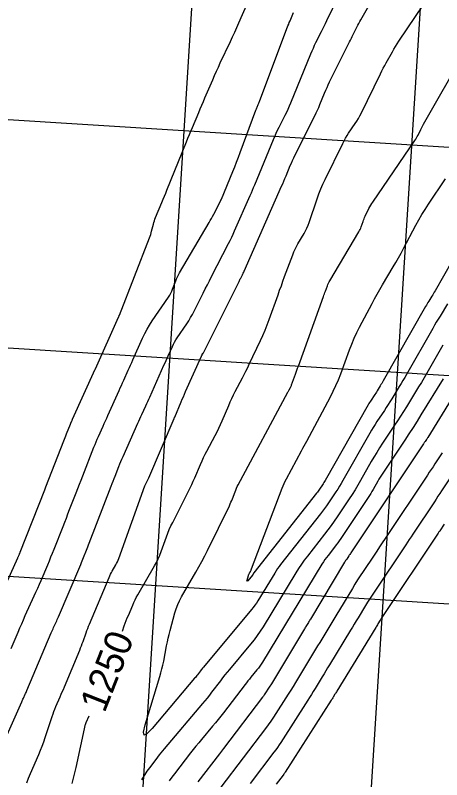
# Model space of a CAD drawing. Extents: x 658976 to 668721, y 639543 to 647196.
# Drawn here: x 661943.1 to 662036.6, y 641838 to 642005.8 of the extents above; entities that cross this region are included whole.
import ezdxf

# ---------------------------------------------------------------- set-up
doc = ezdxf.new("R2010")
doc.units = 0
for name, color, linetype in [('Ex_Contour Labels', 7, 'Continuous'), ('Ex_Major Contours', 7, 'Continuous'), ('Ex_Minor Contours', 7, 'Continuous'), ('R_Grid', 7, 'Continuous')]:
    doc.layers.add(name, color=color, linetype=linetype)

msp = doc.modelspace()

# ---------------------------------------------------------------- linework, layer by layer
at = {"layer": 'Ex_Major Contours'}
for points in [[(661966.58, 641870.64), (661966.98, 641871.77), (661967.19, 641872.35), (661967.41, 641872.93), (661967.63, 641873.5), (661967.87, 641874.07), (661968.82, 641876.35), (661969.07, 641876.91), (661969.34, 641877.47), (661969.62, 641878.02), (661969.92, 641878.55), (661973.62, 641884.96), (661974.03, 641885.71), (661974.41, 641886.48), (661974.75, 641887.27), (661975.06, 641888.07), (661976.23, 641891.31), (661976.54, 641892.12), (661976.86, 641892.91), (661977.22, 641893.7), (661977.6, 641894.47), (661981.08, 641901.31), (661981.44, 641902.03), (661981.79, 641902.76), (661982.12, 641903.5), (661982.45, 641904.24), (661983.72, 641907.22), (661984.04, 641907.96), (661984.38, 641908.69), (661984.74, 641909.42), (661985.11, 641910.13), (661986.93, 641913.56), (661987.33, 641914.35), (661987.73, 641915.15), (661988.1, 641915.96), (661988.46, 641916.77), (661989.88, 641920.15), (661990.21, 641920.92), (661990.57, 641921.69), (661990.94, 641922.45), (661991.32, 641923.2), (661992.9, 641926.19), (661993.29, 641926.94), (661993.67, 641927.7), (661994.05, 641928.46), (661994.41, 641929.22), (661996.85, 641934.41), (661997.37, 641935.53), (661997.85, 641936.67), (661998.31, 641937.82), (661998.74, 641938.98), (662000.7, 641944.42), (662001.06, 641945.43), (662001.43, 641946.43), (662001.79, 641947.44), (662002.16, 641948.45), (662003.92, 641953.23), (662004.16, 641953.85), (662004.43, 641954.45), (662004.73, 641955.04), (662005.05, 641955.62), (662006.41, 641957.9), (662006.74, 641958.48), (662007.03, 641959.07), (662007.29, 641959.68), (662007.52, 641960.3), (662009.28, 641965.52), (662009.66, 641966.6), (662010.08, 641967.66), (662010.53, 641968.7), (662011.01, 641969.73), (662014.9, 641977.67), (662015.19, 641978.25), (662015.5, 641978.81), (662015.84, 641979.36), (662016.19, 641979.89), (662017.65, 641982.02), (662018, 641982.56), (662018.33, 641983.11), (662018.64, 641983.67), (662018.94, 641984.25), (662023.17, 641992.95), (662023.47, 641993.56), (662023.78, 641994.17), (662024.11, 641994.77), (662024.44, 641995.36), (662025.79, 641997.74), (662026.13, 641998.33), (662026.49, 641998.92), (662026.85, 641999.49), (662027.22, 642000.07), (662034.36, 642010.77)], [(662036.85, 641933.37), (662036.27, 641932.35), (662033.94, 641928.26), (662033.35, 641927.24), (662032.76, 641926.22), (662032.15, 641925.21), (662031.54, 641924.21), (662028.85, 641919.82), (662028.22, 641918.81), (662027.59, 641917.8), (662026.94, 641916.8), (662026.29, 641915.81), (662023.65, 641911.85), (662023, 641910.86), (662022.36, 641909.85), (662021.75, 641908.83), (662021.15, 641907.81), (662018.79, 641903.66), (662018.2, 641902.64), (662017.59, 641901.63), (662016.96, 641900.63), (662016.32, 641899.64), (662013.7, 641895.71), (662013.03, 641894.74), (662012.35, 641893.78), (662011.65, 641892.83), (662010.93, 641891.89), (662007.15, 641887.1), (662006.47, 641886.21), (662005.82, 641885.29), (662005.19, 641884.36), (662004.59, 641883.41), (661997.43, 641871.59), (661996.8, 641870.6), (661996.14, 641869.63), (661995.44, 641868.69), (661994.7, 641867.77), (661990.07, 641862.23), (661989.56, 641861.61), (661989.05, 641860.99), (661988.56, 641860.36), (661988.07, 641859.73), (661986.13, 641857.19), (661985.64, 641856.56), (661985.15, 641855.93), (661984.64, 641855.31), (661984.13, 641854.7), (661975.74, 641844.76), (661975.37, 641844.32), (661975.01, 641843.88), (661974.66, 641843.44), (661974.3, 641842.99), (661972.77, 641841.01), (661972.49, 641840.64), (661972.22, 641840.27), (661971.96, 641839.89), (661971.71, 641839.51), (661970.72, 641837.96)], [(662037.13, 641894.07), (662036.17, 641892.63), (662036.09, 641892.51), (662036.01, 641892.39), (662035.93, 641892.27), (662035.85, 641892.15), (662023.6, 641873.79), (662023.47, 641873.59), (662023.34, 641873.4), (662023.22, 641873.2), (662023.1, 641873), (662022.61, 641872.19), (662022.49, 641871.99), (662022.37, 641871.79), (662022.25, 641871.59), (662022.13, 641871.39), (662013.61, 641857.44), (662013.5, 641857.27), (662013.4, 641857.11), (662013.3, 641856.94), (662013.2, 641856.78), (662012.8, 641856.11), (662012.7, 641855.95), (662012.6, 641855.78), (662012.5, 641855.62), (662012.39, 641855.45), (662002.28, 641839.67), (662002.17, 641839.51), (662002.07, 641839.35), (662001.95, 641839.2), (662001.84, 641839.04), (662000.3, 641837.02)], [(661955.52, 641837.17), (661955.85, 641838.33), (661956.15, 641839.49), (661956.42, 641840.66), (661958.5, 641850.19), (661958.51, 641850.22), (661958.51, 641850.25), (661958.52, 641850.28), (661958.53, 641850.31), (661958.57, 641850.43), (661958.58, 641850.45), (661958.59, 641850.48), (661958.6, 641850.51), (661958.61, 641850.54), (661959.25, 641852.03)]]:
    msp.add_lwpolyline(points, dxfattribs=at)
at = {"layer": 'Ex_Minor Contours'}
for points in [[(661945.58, 641837.33), (661945.99, 641838.34), (661946.41, 641839.35), (661948.21, 641843.54), (661948.59, 641844.46), (661948.96, 641845.4), (661949.3, 641846.33), (661949.63, 641847.28), (661951.17, 641851.88), (661951.36, 641852.43), (661951.56, 641852.98), (661951.77, 641853.52), (661952, 641854.06), (661952.92, 641856.21), (661953.15, 641856.75), (661953.38, 641857.29), (661953.61, 641857.82), (661953.84, 641858.36), (661957.21, 641866.45), (661957.4, 641866.92), (661957.58, 641867.39), (661957.76, 641867.87), (661957.93, 641868.34), (661958.6, 641870.26), (661958.78, 641870.74), (661958.95, 641871.21), (661959.14, 641871.68), (661959.33, 641872.15), (661963.66, 641882.42), (661963.81, 641882.78), (661963.98, 641883.12), (661964.16, 641883.47), (661964.34, 641883.81), (661965.12, 641885.15), (661965.3, 641885.49), (661965.47, 641885.83), (661965.63, 641886.19), (661965.77, 641886.55), (661971.52, 641902.5), (661971.58, 641902.66), (661971.64, 641902.81), (661971.71, 641902.96), (661971.78, 641903.1), (661972.08, 641903.69), (661972.15, 641903.83), (661972.22, 641903.98), (661972.29, 641904.13), (661972.35, 641904.28), (661977.89, 641917.27), (661977.91, 641917.3), (661977.92, 641917.33), (661977.93, 641917.35), (661977.95, 641917.38), (661978, 641917.48), (661978.01, 641917.51), (661978.03, 641917.54), (661978.04, 641917.56), (661978.05, 641917.59), (661979.46, 641920.93), (661979.7, 641921.5), (661979.94, 641922.06), (661980.19, 641922.62), (661980.44, 641923.18), (661983.91, 641930.95), (661983.94, 641931.02), (661983.97, 641931.08), (661984.03, 641931.21), (661984.05, 641931.25), (661984.06, 641931.28), (661984.08, 641931.31), (661984.1, 641931.34), (661984.23, 641931.53), (661984.26, 641931.57), (661984.29, 641931.62), (661984.31, 641931.66), (661984.34, 641931.71), (661992.15, 641947.36), (661992.25, 641947.55), (661992.34, 641947.73), (661992.43, 641947.92), (661992.53, 641948.1), (661992.91, 641948.83), (661993, 641949.02), (661993.09, 641949.2), (661993.18, 641949.39), (661993.26, 641949.58), (662001.49, 641968.25), (662001.74, 641968.81), (662001.98, 641969.37), (662002.22, 641969.94), (662002.46, 641970.51), (662003.4, 641972.78), (662003.64, 641973.34), (662003.89, 641973.91), (662004.15, 641974.46), (662004.42, 641975.02), (662008.77, 641983.73), (662009.07, 641984.34), (662009.35, 641984.95), (662009.63, 641985.57), (662009.89, 641986.19), (662010.91, 641988.69), (662011.18, 641989.31), (662011.45, 641989.93), (662011.73, 641990.54), (662012.03, 641991.14), (662016.4, 641999.92), (662016.6, 642000.33), (662016.8, 642000.73), (662017, 642001.14), (662017.2, 642001.55), (662017.99, 642003.18), (662018.19, 642003.58), (662018.4, 642003.98), (662018.62, 642004.38), (662018.84, 642004.78), (662026.11, 642017.5)], [(661937.41, 641839.27), (661944.47, 641855.08), (661944.57, 641855.29), (661944.66, 641855.5), (661944.75, 641855.71), (661944.85, 641855.92), (661945.23, 641856.75), (661945.32, 641856.96), (661945.42, 641857.17), (661945.51, 641857.38), (661945.6, 641857.59), (661950.96, 641870.24), (661951.09, 641870.54), (661951.22, 641870.83), (661951.35, 641871.13), (661951.48, 641871.42), (661952.02, 641872.6), (661952.15, 641872.89), (661952.28, 641873.18), (661952.41, 641873.48), (661952.53, 641873.78), (661957.43, 641885.26), (661957.59, 641885.65), (661957.75, 641886.04), (661957.91, 641886.42), (661958.06, 641886.81), (661958.67, 641888.37), (661958.82, 641888.76), (661958.98, 641889.15), (661959.13, 641889.54), (661959.28, 641889.93), (661964.11, 641902.46), (661964.32, 641903), (661964.53, 641903.54), (661964.74, 641904.08), (661964.95, 641904.62), (661965.8, 641906.78), (661966.02, 641907.32), (661966.24, 641907.86), (661966.47, 641908.39), (661966.7, 641908.92), (661969.98, 641916.25), (661970.2, 641916.73), (661970.41, 641917.21), (661970.62, 641917.69), (661970.84, 641918.16), (661971.7, 641920.07), (661971.91, 641920.55), (661972.12, 641921.02), (661972.34, 641921.5), (661972.55, 641921.98), (661975.69, 641928.99), (661975.92, 641929.5), (661976.15, 641930.01), (661976.38, 641930.52), (661976.6, 641931.03), (661977.52, 641933.07), (661977.76, 641933.57), (661978.02, 641934.06), (661978.3, 641934.54), (661978.61, 641935.01), (661980.68, 641938.07), (661981.12, 641938.74), (661981.54, 641939.42), (661981.93, 641940.12), (661982.3, 641940.83), (661984.29, 641944.81), (661984.74, 641945.72), (661985.2, 641946.62), (661985.65, 641947.52), (661986.12, 641948.41), (661989.86, 641955.68), (661990.21, 641956.36), (661990.54, 641957.05), (661990.87, 641957.74), (661991.18, 641958.44), (661994.6, 641966.19), (661994.86, 641966.78), (661995.11, 641967.38), (661995.36, 641967.97), (661995.61, 641968.57), (661999.72, 641978.51), (662000.01, 641979.19), (662000.31, 641979.87), (662000.62, 641980.54), (662000.95, 641981.2), (662002.27, 641983.86), (662002.6, 641984.53), (662002.91, 641985.2), (662003.21, 641985.88), (662003.5, 641986.56), (662007.91, 641997.33), (662008.17, 641997.95), (662008.45, 641998.57), (662008.73, 641999.18), (662009.03, 641999.78), (662010.23, 642002.19), (662010.53, 642002.8), (662010.82, 642003.4), (662011.12, 642004), (662011.42, 642004.61), (662014.14, 642010.23)], [(661937.78, 641873.8), (661943.62, 641886.68), (661943.66, 641886.78), (661943.71, 641886.89), (661943.76, 641886.99), (661943.8, 641887.1), (661943.98, 641887.52), (661944.02, 641887.62), (661944.07, 641887.73), (661944.11, 641887.83), (661944.15, 641887.94), (661949.53, 641901.62), (661949.55, 641901.67), (661949.57, 641901.73), (661949.59, 641901.78), (661949.61, 641901.83), (661949.69, 641902.05), (661949.71, 641902.1), (661949.73, 641902.15), (661949.75, 641902.21), (661949.78, 641902.26), (661953.74, 641912.36), (661953.9, 641912.74), (661954.04, 641913.12), (661954.19, 641913.51), (661954.34, 641913.89), (661955.15, 641916.01), (661955.19, 641916.1), (661955.23, 641916.2), (661955.27, 641916.3), (661955.31, 641916.39), (661955.47, 641916.78), (661955.51, 641916.87), (661955.55, 641916.97), (661955.59, 641917.06), (661955.64, 641917.16), (661960.56, 641928.1), (661960.57, 641928.11), (661960.57, 641928.11), (661960.57, 641928.11), (661960.58, 641928.11), (661960.6, 641928.11), (661960.6, 641928.11), (661960.61, 641928.11), (661960.61, 641928.11), (661960.61, 641928.11), (661960.64, 641928.16), (661960.64, 641928.17), (661960.65, 641928.17), (661960.65, 641928.18), (661960.65, 641928.19), (661965.74, 641939.51), (661965.76, 641939.55), (661965.78, 641939.59), (661965.79, 641939.63), (661965.8, 641939.66), (661965.85, 641939.82), (661965.86, 641939.86), (661965.88, 641939.89), (661965.89, 641939.93), (661965.9, 641939.97), (661972.51, 641956.93), (661972.64, 641957.3), (661972.77, 641957.67), (661972.88, 641958.04), (661972.98, 641958.42), (661973.36, 641959.94), (661973.46, 641960.31), (661973.58, 641960.68), (661973.71, 641961.05), (661973.85, 641961.41), (661975.22, 641964.72), (661975.5, 641965.39), (661975.78, 641966.07), (661976.06, 641966.74), (661976.33, 641967.41), (661980.63, 641977.99), (661980.95, 641978.79), (661981.28, 641979.58), (661981.61, 641980.37), (661981.94, 641981.17), (661983.3, 641984.44), (661983.64, 641985.25), (661983.98, 641986.06), (661984.33, 641986.87), (661984.67, 641987.68), (661986.38, 641991.63), (661986.78, 641992.55), (661987.2, 641993.48), (661987.61, 641994.39), (661988.04, 641995.31), (661990.26, 642000.01), (661990.74, 642001.03), (661991.21, 642002.06), (661991.67, 642003.09), (661992.12, 642004.12), (661993.99, 642008.44)], [(661942.16, 641866.8), (661943.69, 641870.41), (661944.08, 641871.32), (661944.47, 641872.22), (661944.86, 641873.11), (661945.27, 641874.01), (661947.23, 641878.34), (661947.61, 641879.19), (661947.99, 641880.04), (661948.36, 641880.89), (661948.73, 641881.75), (661950.18, 641885.17), (661950.54, 641886.03), (661950.9, 641886.89), (661951.25, 641887.75), (661951.59, 641888.61), (661953.55, 641893.59), (661953.91, 641894.51), (661954.27, 641895.44), (661954.63, 641896.36), (661954.99, 641897.29), (661956.42, 641901), (661956.78, 641901.92), (661957.13, 641902.85), (661957.5, 641903.77), (661957.86, 641904.7), (661960.33, 641910.97), (661960.56, 641911.56), (661960.8, 641912.15), (661961.05, 641912.73), (661961.31, 641913.31), (661962.34, 641915.63), (661962.6, 641916.21), (661962.86, 641916.79), (661963.12, 641917.37), (661963.38, 641917.94), (661965.85, 641923.44), (661966.1, 641923.99), (661966.35, 641924.55), (661966.6, 641925.11), (661966.85, 641925.67), (661967.85, 641927.89), (661968.1, 641928.45), (661968.35, 641929.01), (661968.6, 641929.57), (661968.85, 641930.12), (661971.01, 641934.93), (661971.47, 641935.9), (661971.98, 641936.85), (661972.53, 641937.78), (661973.11, 641938.69), (661976.67, 641943.93), (661976.94, 641944.35), (661977.18, 641944.77), (661977.39, 641945.21), (661977.58, 641945.67), (661978.27, 641947.5), (661978.46, 641947.96), (661978.66, 641948.4), (661978.88, 641948.84), (661979.12, 641949.27), (661985.59, 641960.26), (661985.85, 641960.72), (661986.1, 641961.17), (661986.35, 641961.63), (661986.59, 641962.1), (661988, 641964.82), (661988.01, 641964.85), (661988.03, 641964.88), (661988.05, 641964.92), (661988.06, 641964.95), (661988.22, 641965.32), (661988.24, 641965.35), (661988.25, 641965.38), (661988.26, 641965.4), (661988.27, 641965.43), (661990.78, 641971.52), (661991.2, 641972.54), (661991.61, 641973.57), (661992.01, 641974.6), (661992.4, 641975.64), (661995.86, 641984.96), (661995.92, 641985.12), (661995.98, 641985.27), (661996.05, 641985.43), (661996.11, 641985.58), (661996.38, 641986.2), (661996.44, 641986.36), (661996.51, 641986.52), (661996.57, 641986.67), (661996.63, 641986.83), (662002.89, 642003.44), (662003.04, 642003.82), (662003.18, 642004.19), (662003.34, 642004.56), (662003.49, 642004.93), (662004.13, 642006.4)], [(662037.9, 641942.46), (662036.25, 641939.77), (662035.84, 641939.1), (662035.43, 641938.42), (662035.03, 641937.73), (662034.64, 641937.05), (662028.88, 641926.94), (662028.49, 641926.27), (662028.1, 641925.6), (662027.7, 641924.94), (662027.3, 641924.27), (662025.65, 641921.58), (662025.26, 641920.95), (662024.86, 641920.32), (662024.45, 641919.69), (662024.04, 641919.07), (662022.39, 641916.59), (662021.98, 641915.96), (662021.58, 641915.33), (662021.2, 641914.7), (662020.82, 641914.05), (662014.92, 641903.67), (662014.55, 641903.04), (662014.17, 641902.41), (662013.79, 641901.79), (662013.38, 641901.18), (662011.76, 641898.75), (662011.35, 641898.14), (662010.93, 641897.55), (662010.49, 641896.96), (662010.04, 641896.38), (662001.28, 641885.25), (662000.93, 641884.79), (662000.6, 641884.33), (662000.27, 641883.85), (661999.97, 641883.36), (661996.29, 641877.29), (661995.97, 641876.78), (661995.63, 641876.29), (661995.27, 641875.8), (661994.89, 641875.33), (661984.32, 641862.69), (661984.16, 641862.49), (661984, 641862.29), (661983.84, 641862.09), (661983.68, 641861.88), (661983.05, 641861.06), (661982.89, 641860.86), (661982.73, 641860.65), (661982.57, 641860.45), (661982.4, 641860.26), (661973.08, 641849.21), (661971.95, 641848.04), (661971.32, 641847.78), (661971.19, 641848.45), (661971.57, 641850.04), (661974.79, 641860.66), (661975.03, 641861.48), (661975.25, 641862.32), (661975.44, 641863.15), (661975.62, 641864), (661976.26, 641867.38), (661976.43, 641868.23), (661976.62, 641869.07), (661976.82, 641869.9), (661977.04, 641870.74), (661978.09, 641874.63), (661978.37, 641875.54), (661978.71, 641876.43), (661979.1, 641877.3), (661979.55, 641878.14), (661982.67, 641883.54), (661983.34, 641884.72), (661983.99, 641885.92), (661984.62, 641887.12), (661985.23, 641888.34), (661990.03, 641898.14), (661990.21, 641898.52), (661990.38, 641898.89), (661990.54, 641899.27), (661990.69, 641899.66), (661991.28, 641901.2), (661991.43, 641901.58), (661991.59, 641901.96), (661991.77, 641902.33), (661991.96, 641902.7), (662002.86, 641923.03), (662002.93, 641923.17), (662003, 641923.3), (662003.08, 641923.44), (662003.15, 641923.57), (662003.44, 641924.11), (662003.51, 641924.25), (662003.57, 641924.38), (662003.63, 641924.52), (662003.69, 641924.67), (662004.54, 641927), (662004.7, 641927.44), (662004.85, 641927.88), (662005.01, 641928.31), (662005.17, 641928.75), (662010.68, 641944.08), (662010.78, 641944.37), (662010.89, 641944.66), (662010.99, 641944.96), (662011.1, 641945.25), (662011.53, 641946.41), (662011.64, 641946.7), (662011.77, 641946.98), (662011.91, 641947.26), (662012.06, 641947.53), (662018.45, 641958.24), (662018.6, 641958.51), (662018.74, 641958.78), (662018.86, 641959.06), (662018.96, 641959.35), (662019.36, 641960.52), (662019.46, 641960.81), (662019.57, 641961.09), (662019.69, 641961.37), (662019.82, 641961.65), (662020.65, 641963.35), (662020.85, 641963.72), (662021.05, 641964.09), (662021.26, 641964.44), (662021.49, 641964.79), (662030.74, 641978.31), (662030.92, 641978.59), (662031.1, 641978.88), (662031.26, 641979.18), (662031.42, 641979.48), (662032.01, 641980.7), (662032.16, 641981), (662032.31, 641981.3), (662032.48, 641981.6), (662032.64, 641981.9), (662041.58, 641997.6)], [(662044.31, 641961.4), (662035.14, 641945.31), (662034.97, 641945.03), (662034.8, 641944.74), (662034.63, 641944.45), (662034.46, 641944.16), (662033.76, 641943.02), (662033.58, 641942.74), (662033.41, 641942.45), (662033.24, 641942.16), (662033.08, 641941.87), (662023.76, 641925.52), (662023.6, 641925.25), (662023.44, 641924.98), (662023.28, 641924.71), (662023.12, 641924.44), (662022.45, 641923.35), (662022.29, 641923.09), (662022.13, 641922.84), (662021.97, 641922.58), (662021.8, 641922.33), (662021.13, 641921.32), (662020.96, 641921.07), (662020.8, 641920.82), (662020.65, 641920.56), (662020.49, 641920.3), (662011.05, 641903.69), (662010.9, 641903.44), (662010.76, 641903.2), (662010.61, 641902.96), (662010.45, 641902.72), (662009.83, 641901.78), (662009.67, 641901.55), (662009.5, 641901.32), (662009.33, 641901.09), (662009.16, 641900.87), (661995.41, 641883.41), (661995.39, 641883.38), (661995.37, 641883.36), (661995.36, 641883.33), (661995.34, 641883.31), (661995.15, 641882.99), (661995.13, 641882.97), (661995.12, 641882.94), (661995.1, 641882.92), (661995.08, 641882.89), (661994.07, 641881.69), (661993.96, 641881.57), (661993.9, 641881.55), (661993.89, 641881.62), (661993.92, 641881.77), (661994.2, 641882.82), (661994.22, 641882.88), (661994.25, 641882.95), (661994.27, 641883.01), (661994.31, 641883.07), (661994.45, 641883.32), (661994.48, 641883.38), (661994.52, 641883.44), (661994.55, 641883.5), (661994.58, 641883.56), (661994.76, 641883.94), (661994.8, 641884.03), (661994.84, 641884.11), (661994.88, 641884.2), (661994.91, 641884.28), (662001.62, 641901.97), (662001.83, 641902.49), (662002.05, 641903.01), (662002.3, 641903.52), (662002.56, 641904.03), (662005.87, 641910.21), (662006.16, 641910.74), (662006.44, 641911.27), (662006.72, 641911.8), (662007.01, 641912.33), (662012.19, 641922.03), (662012.83, 641923.27), (662013.42, 641924.52), (662013.96, 641925.8), (662014.46, 641927.09), (662016.38, 641932.36), (662016.87, 641933.63), (662017.4, 641934.89), (662017.97, 641936.13), (662018.59, 641937.35), (662021.34, 641942.55), (662021.89, 641943.57), (662022.45, 641944.58), (662023.03, 641945.59), (662023.61, 641946.58), (662025.99, 641950.55), (662026.57, 641951.55), (662027.15, 641952.55), (662027.71, 641953.56), (662028.26, 641954.58), (662030.96, 641959.68), (662031.61, 641960.86), (662032.28, 641962.02), (662032.98, 641963.17), (662033.71, 641964.3), (662037.42, 641969.91)], [(662036.91, 641925.97), (662032.05, 641918.05), (662031.19, 641916.66), (662030.32, 641915.29), (662029.43, 641913.91), (662028.53, 641912.55), (662023.67, 641905.26), (662023.39, 641904.83), (662023.11, 641904.39), (662022.85, 641903.95), (662022.59, 641903.5), (662021.57, 641901.71), (662021.31, 641901.26), (662021.04, 641900.82), (662020.77, 641900.39), (662020.48, 641899.95), (662014.47, 641890.93), (662014.14, 641890.45), (662013.81, 641889.98), (662013.46, 641889.52), (662013.11, 641889.06), (662011.67, 641887.23), (662011.32, 641886.77), (662010.98, 641886.3), (662010.66, 641885.82), (662010.35, 641885.33), (661997.3, 641863.79), (661997.02, 641863.35), (661996.73, 641862.92), (661996.42, 641862.51), (661996.09, 641862.1), (661994.76, 641860.5), (661994.43, 641860.1), (661994.1, 641859.7), (661993.78, 641859.29), (661993.46, 641858.88), (661988.74, 641852.7), (661988.16, 641851.95), (661987.57, 641851.21), (661986.97, 641850.47), (661986.36, 641849.74), (661983.92, 641846.85), (661983.31, 641846.12), (661982.71, 641845.38), (661982.12, 641844.64), (661981.53, 641843.9), (661977.98, 641839.33), (661977.39, 641838.56), (661976.83, 641837.77)], [(662041.22, 641925.61), (662033.55, 641913.13), (662033.48, 641913.01), (662033.4, 641912.9), (662033.33, 641912.78), (662033.25, 641912.66), (662032.95, 641912.2), (662032.87, 641912.08), (662032.79, 641911.97), (662032.71, 641911.85), (662032.64, 641911.74), (662016.69, 641887.81), (662016.57, 641887.63), (662016.46, 641887.46), (662016.34, 641887.29), (662016.23, 641887.12), (662015.77, 641886.43), (662015.65, 641886.25), (662015.54, 641886.08), (662015.43, 641885.9), (662015.32, 641885.73), (662007.8, 641873.25), (662007.69, 641873.07), (662007.59, 641872.89), (662007.48, 641872.71), (662007.37, 641872.53), (662006.94, 641871.83), (662006.83, 641871.65), (662006.72, 641871.47), (662006.61, 641871.29), (662006.51, 641871.11), (661999.24, 641859.06), (661999.09, 641858.81), (661998.93, 641858.56), (661998.78, 641858.32), (661998.62, 641858.07), (661997.99, 641857.09), (661997.83, 641856.84), (661997.67, 641856.6), (661997.5, 641856.37), (661997.33, 641856.13), (661988.77, 641844.84), (661988.55, 641844.55), (661988.32, 641844.25), (661988.1, 641843.96), (661987.87, 641843.67), (661983.11, 641837.55)], [(662036.74, 641909.78), (662035.11, 641907.32), (662034.7, 641906.7), (662034.29, 641906.08), (662033.88, 641905.47), (662033.47, 641904.85), (662024.19, 641890.92), (662023.58, 641890.01), (662022.98, 641889.11), (662022.37, 641888.2), (662021.77, 641887.29), (662019.35, 641883.67), (662018.75, 641882.76), (662018.16, 641881.84), (662017.58, 641880.92), (662017.01, 641879.99), (662013.4, 641873.99), (662012.96, 641873.26), (662012.51, 641872.53), (662012.07, 641871.79), (662011.62, 641871.06), (662009.84, 641868.14), (662009.39, 641867.41), (662008.95, 641866.68), (662008.51, 641865.95), (662008.06, 641865.22), (662004.53, 641859.36), (662004.01, 641858.5), (662003.48, 641857.64), (662002.95, 641856.79), (662002.41, 641855.94), (662000.23, 641852.54), (661999.68, 641851.7), (661999.11, 641850.87), (661998.53, 641850.05), (661997.93, 641849.24), (661988.17, 641836.37)], [(662040.91, 641907.95), (662036.57, 641901.38), (662036.18, 641900.79), (662035.79, 641900.2), (662035.4, 641899.61), (662035, 641899.02), (662030.28, 641891.93), (662029.89, 641891.34), (662029.49, 641890.75), (662029.1, 641890.16), (662028.71, 641889.57), (662021.63, 641878.95), (662021.19, 641878.29), (662020.75, 641877.62), (662020.33, 641876.94), (662019.92, 641876.26), (662018.27, 641873.53), (662017.86, 641872.84), (662017.44, 641872.16), (662017.03, 641871.48), (662016.61, 641870.8), (662011.97, 641863.19), (662011.57, 641862.54), (662011.18, 641861.89), (662010.79, 641861.25), (662010.39, 641860.6), (662008.83, 641858), (662008.44, 641857.36), (662008.04, 641856.71), (662007.64, 641856.07), (662007.23, 641855.43), (662001.31, 641846.19), (662000.95, 641845.65), (662000.59, 641845.11), (662000.21, 641844.58), (661999.82, 641844.06), (661994.6, 641837.18)]]:
    msp.add_lwpolyline(points, dxfattribs=at)
at = {"layer": 'R_Grid'}
for p, q in [((661970.74, 641830.75), (661986.41, 642080.26)), ((662020.64, 641827.62), (662036.31, 642077.12)), ((661630.83, 642002.39), (663127.88, 641908.37)), ((661627.7, 641952.49), (663124.75, 641858.47)), ((661624.56, 641902.59), (663121.61, 641808.57))]:
    msp.add_line(p, q, dxfattribs=at)

# ---------------------------------------------------------------- texts
at = {"layer": 'Ex_Contour Labels'}
msp.add_text('1250', height=6, rotation=68.5028, dxfattribs=at).set_placement((661962.65, 641852.48))

doc.saveas('drawing.dxf')
